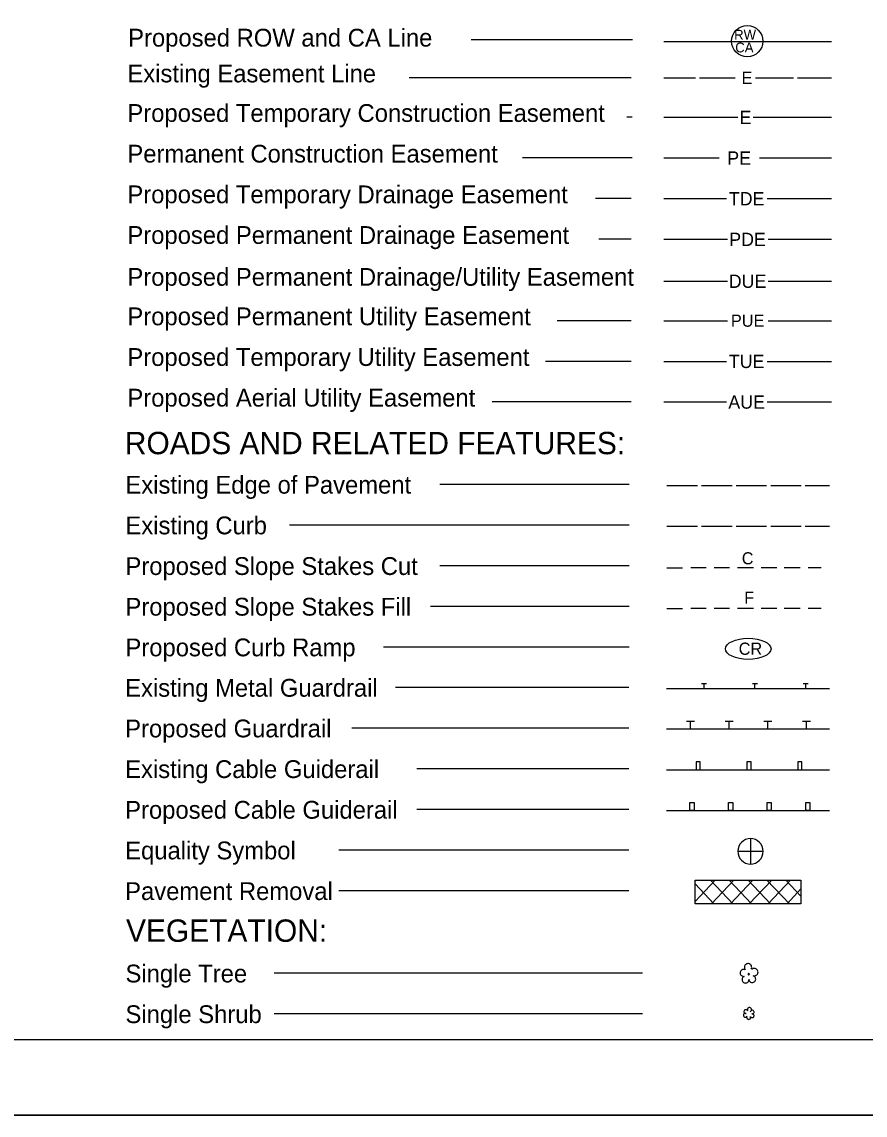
# Model space of a CAD drawing. Extents: x 754056.72 to 754059.56, y 596603.78 to 596605.61.
# Drawn here: x 754057.422 to 754058.119, y 596603.778 to 596604.682 of the extents above; entities that cross this region are included whole.
import ezdxf

# ---------------------------------------------------------------- set-up
doc = ezdxf.new("R2010")
doc.units = 0
for name, color, linetype in [('P_RDY_Easement_Permanent', 7, 'Continuous'), ('P_RDY_Easement_Permanent_Drainage_Utility', 7, 'Continuous'), ('P_RDY_WCC_CELL', 7, 'Continuous'), ('Sheet_Plan', 7, 'Continuous'), ('Sheet_Plot_Border_Outside_CELL', 7, 'Continuous'), ('Sheet_Symbology', 7, 'Continuous'), ('z - Construction', 7, 'Continuous')]:
    doc.layers.add(name, color=color, linetype=linetype)

msp = doc.modelspace()

# ---------------------------------------------------------------- linework, layer by layer
at = {"layer": 'P_RDY_Easement_Permanent'}
for p, q in [((754057.95295, 596604.56986), (754057.99875, 596604.56986)), ((754058.03205, 596604.56986), (754058.07785, 596604.56986)), ((754058.07785, 596604.56986), (754058.09168, 596604.56986))]:
    msp.add_line(p, q, dxfattribs=at)
at = {"layer": 'P_RDY_Easement_Permanent_Drainage_Utility'}
for p, q in [((754057.95295, 596604.46799), (754058.00559, 596604.46799)), ((754058.03922, 596604.46799), (754058.09168, 596604.46799))]:
    msp.add_line(p, q, dxfattribs=at)
at = {"layer": 'P_RDY_WCC_CELL'}
msp.add_ellipse((754058.02274, 596604.16393), major_axis=(0.01886, 0), ratio=0.462467, dxfattribs=at)
at = {"layer": 'Sheet_Plan'}
msp.add_line((754056.78734, 596603.84076), (754059.49562, 596603.84076), dxfattribs=at)
at = {"layer": 'Sheet_Plot_Border_Outside_CELL'}
msp.add_lwpolyline([(754056.72484, 596605.61159), (754059.55817, 596605.61159), (754059.55817, 596603.77826), (754056.72484, 596603.77826)], close=True, dxfattribs=at)
at = {"layer": 'Sheet_Symbology'}
for p, q in [((754057.92706, 596604.66751), (754057.79361, 596604.66751)), ((754057.95297, 596604.66621), (754058.0917, 596604.66621)), ((754057.926, 596604.63621), (754057.74229, 596604.63621)), ((754057.95295, 596604.63621), (754057.97904, 596604.63621)), ((754057.9824, 596604.63621), (754058.01183, 596604.63621)), ((754058.02864, 596604.63621), (754058.06017, 596604.63621)), ((754058.06354, 596604.63621), (754058.09168, 596604.63621)), ((754057.92664, 596604.60349), (754057.92241, 596604.60349)), ((754057.95295, 596604.60349), (754057.95735, 596604.60349)), ((754057.95735, 596604.60349), (754058.0141, 596604.60349)), ((754058.02671, 596604.60349), (754058.08346, 596604.60349)), ((754058.08346, 596604.60349), (754058.09168, 596604.60349)), ((754057.92664, 596604.56986), (754057.83617, 596604.56986)), ((754057.926, 596604.53623), (754057.89657, 596604.53623)), ((754057.95295, 596604.53623), (754057.95859, 596604.53623)), ((754057.95859, 596604.53623), (754058.00483, 596604.53623)), ((754058.03846, 596604.53623), (754058.0847, 596604.53623)), ((754058.0847, 596604.53623), (754058.09168, 596604.53623)), ((754057.926, 596604.5026), (754057.89908, 596604.5026)), ((754057.95295, 596604.5026), (754057.95934, 596604.5026)), ((754057.95934, 596604.5026), (754058.00559, 596604.5026)), ((754058.03922, 596604.5026), (754058.08546, 596604.5026)), ((754058.08546, 596604.5026), (754058.09168, 596604.5026)), ((754057.926, 596604.43532), (754057.86477, 596604.43532)), ((754057.95295, 596604.43532), (754057.95941, 596604.43532)), ((754057.95941, 596604.43532), (754058.00565, 596604.43532)), ((754058.03928, 596604.43532), (754058.08552, 596604.43532)), ((754058.08552, 596604.43532), (754058.09168, 596604.43532)), ((754057.926, 596604.40169), (754057.85514, 596604.40169)), ((754057.95295, 596604.40169), (754057.95859, 596604.40169)), ((754057.95859, 596604.40169), (754058.00483, 596604.40169)), ((754058.03846, 596604.40169), (754058.0847, 596604.40169)), ((754058.0847, 596604.40169), (754058.09168, 596604.40169)), ((754057.926, 596604.36806), (754057.81088, 596604.36806)), ((754057.95295, 596604.36806), (754057.95859, 596604.36806)), ((754057.95859, 596604.36806), (754058.00483, 596604.36806)), ((754058.03846, 596604.36806), (754058.0847, 596604.36806)), ((754058.0847, 596604.36806), (754058.09168, 596604.36806)), ((754057.92438, 596604.29991), (754057.76759, 596604.29991)), ((754057.95554, 596604.29895), (754057.98076, 596604.29895)), ((754057.98413, 596604.29895), (754058.00935, 596604.29895)), ((754058.01271, 596604.29895), (754058.03794, 596604.29895)), ((754058.0413, 596604.29895), (754058.06652, 596604.29895)), ((754058.06989, 596604.29895), (754058.09006, 596604.29895)), ((754057.92438, 596604.26628), (754057.64331, 596604.26628)), ((754057.95554, 596604.26531), (754057.98076, 596604.26531)), ((754057.98413, 596604.26531), (754058.00935, 596604.26531)), ((754058.01271, 596604.26531), (754058.03794, 596604.26531)), ((754058.0413, 596604.26531), (754058.06652, 596604.26531)), ((754058.06989, 596604.26531), (754058.09006, 596604.26531)), ((754057.92438, 596604.23265), (754057.76768, 596604.23265)), ((754057.95554, 596604.23088), (754057.96832, 596604.23088)), ((754057.98799, 596604.23088), (754057.9753, 596604.23088)), ((754058.00733, 596604.23088), (754057.99455, 596604.23088)), ((754058.02709, 596604.23088), (754058.01397, 596604.23088)), ((754058.04634, 596604.23088), (754058.03331, 596604.23088)), ((754058.06577, 596604.23088), (754058.05257, 596604.23088)), ((754058.08309, 596604.23088), (754058.07232, 596604.23088)), ((754057.92438, 596604.19902), (754057.76003, 596604.19902)), ((754057.95554, 596604.19725), (754057.96832, 596604.19725)), ((754057.98799, 596604.19725), (754057.9753, 596604.19725)), ((754058.00733, 596604.19725), (754057.99455, 596604.19725)), ((754058.02709, 596604.19725), (754058.01397, 596604.19725)), ((754058.04634, 596604.19725), (754058.03331, 596604.19725)), ((754058.06577, 596604.19725), (754058.05257, 596604.19725)), ((754058.08309, 596604.19725), (754058.07232, 596604.19725)), ((754057.92438, 596604.16539), (754057.72103, 596604.16539)), ((754057.98409, 596604.13519), (754057.9883, 596604.13519)), ((754057.9862, 596604.13099), (754057.9862, 596604.13519)), ((754058.02613, 596604.13519), (754058.03034, 596604.13519)), ((754058.02823, 596604.13099), (754058.02823, 596604.13519)), ((754058.06817, 596604.13519), (754058.07238, 596604.13519)), ((754058.07027, 596604.13099), (754058.07027, 596604.13519)), ((754057.92412, 596604.13196), (754057.73101, 596604.13196)), ((754057.95528, 596604.13099), (754058.0898, 596604.13099)), ((754057.92412, 596604.09833), (754057.69502, 596604.09833)), ((754057.97163, 596604.104), (754057.97836, 596604.104)), ((754057.97499, 596604.09736), (754057.97499, 596604.104)), ((754058.00358, 596604.104), (754058.01031, 596604.104)), ((754058.00694, 596604.09736), (754058.00694, 596604.104)), ((754058.03553, 596604.104), (754058.04225, 596604.104)), ((754058.03889, 596604.09736), (754058.03889, 596604.104)), ((754058.06748, 596604.104), (754058.0742, 596604.104)), ((754058.07084, 596604.09736), (754058.07084, 596604.104)), ((754058.0898, 596604.09736), (754057.95528, 596604.09736)), ((754057.92412, 596604.0647), (754057.74873, 596604.0647)), ((754057.95528, 596604.06373), (754058.0898, 596604.06373)), ((754057.92412, 596604.03106), (754057.74873, 596604.03106)), ((754057.95528, 596604.0301), (754058.0898, 596604.0301)), ((754058.0246, 596604.00695), (754058.0246, 596603.99644)), ((754057.92412, 596603.99743), (754057.68428, 596603.99743)), ((754058.01409, 596603.99644), (754058.0246, 596603.99644)), ((754058.0246, 596603.99644), (754058.0246, 596603.98593)), ((754058.0246, 596603.99644), (754058.03511, 596603.99644)), ((754057.97873, 596603.97269), (754058.06634, 596603.97269)), ((754057.97873, 596603.95302), (754057.97873, 596603.97269)), ((754057.97873, 596603.97168), (754057.97966, 596603.97269)), ((754057.97873, 596603.95495), (754057.9953, 596603.97269)), ((754058.00993, 596603.95302), (754057.99143, 596603.97269)), ((754057.99244, 596603.95302), (754058.01094, 596603.97269)), ((754058.02548, 596603.95302), (754058.00707, 596603.97269)), ((754058.00799, 596603.95302), (754058.02657, 596603.97269)), ((754058.04112, 596603.95302), (754058.02262, 596603.97269)), ((754058.02363, 596603.95302), (754058.04213, 596603.97269)), ((754058.05676, 596603.95302), (754058.03818, 596603.97269)), ((754058.03927, 596603.95302), (754058.05768, 596603.97269)), ((754058.06634, 596603.95932), (754058.05382, 596603.97269)), ((754058.06634, 596603.97269), (754058.06634, 596603.95302)), ((754057.92412, 596603.9638), (754057.68428, 596603.9638)), ((754057.99429, 596603.95302), (754057.97873, 596603.96967)), ((754058.05482, 596603.95302), (754058.06634, 596603.96529)), ((754058.06634, 596603.95302), (754057.97873, 596603.95302)), ((754057.93518, 596603.89562), (754057.63061, 596603.89562)), ((754057.93518, 596603.86199), (754057.63061, 596603.86199))]:
    msp.add_line(p, q, dxfattribs=at)
for points in [[(754057.97962, 596604.06373), (754057.98298, 596604.06373), (754057.98298, 596604.07045), (754057.97962, 596604.07045)], [(754058.02166, 596604.06373), (754058.02502, 596604.06373), (754058.02502, 596604.07045), (754058.02166, 596604.07045)], [(754058.06369, 596604.06373), (754058.06706, 596604.06373), (754058.06706, 596604.07045), (754058.06369, 596604.07045)], [(754057.97455, 596604.03682), (754057.97791, 596604.03682), (754057.97791, 596604.0301), (754057.97455, 596604.0301)], [(754058.0065, 596604.03682), (754058.00986, 596604.03682), (754058.00986, 596604.0301), (754058.0065, 596604.0301)], [(754058.03845, 596604.03682), (754058.04181, 596604.03682), (754058.04181, 596604.0301), (754058.03845, 596604.0301)], [(754058.0704, 596604.03682), (754058.07376, 596604.03682), (754058.07376, 596604.0301), (754058.0704, 596604.0301)]]:
    msp.add_lwpolyline(points, close=True, dxfattribs=at)
for points in [[(754058.0252, 596603.89913), (754058.02547, 596603.89973), (754058.0256, 596603.90032), (754058.02553, 596603.90099), (754058.0254, 596603.90158), (754058.02507, 596603.90218), (754058.02474, 596603.90264), (754058.02421, 596603.90311), (754058.02368, 596603.90337), (754058.02302, 596603.90357), (754058.02242, 596603.90357), (754058.02176, 596603.9035), (754058.02116, 596603.9033), (754058.02064, 596603.90297), (754058.02017, 596603.90251), (754058.01984, 596603.90198), (754058.01958, 596603.90138), (754058.01951, 596603.90079), (754058.01951, 596603.90013), (754058.01964, 596603.89953), (754058.01991, 596603.89894), (754058.0203, 596603.89841), (754058.01977, 596603.89867), (754058.01918, 596603.8988), (754058.01858, 596603.89874), (754058.01799, 596603.8986), (754058.01746, 596603.89834), (754058.01693, 596603.89794), (754058.0166, 596603.89748), (754058.01626, 596603.89695), (754058.01613, 596603.89642), (754058.01607, 596603.89576), (754058.01613, 596603.89516), (754058.0164, 596603.89463), (754058.01673, 596603.8941), (754058.01713, 596603.8937), (754058.01766, 596603.89337), (754058.01819, 596603.89311), (754058.01878, 596603.89304), (754058.01938, 596603.89304), (754058.01885, 596603.89278), (754058.01839, 596603.89238), (754058.01805, 596603.89192), (754058.01779, 596603.89132), (754058.01766, 596603.89073), (754058.01759, 596603.89013), (754058.01772, 596603.88953), (754058.01799, 596603.889), (754058.01832, 596603.88847), (754058.01871, 596603.88808), (754058.01924, 596603.88775), (754058.01984, 596603.88755), (754058.02044, 596603.88748), (754058.02103, 596603.88755), (754058.02163, 596603.88768), (754058.02216, 596603.88801), (754058.02262, 596603.88841), (754058.02295, 596603.88887), (754058.02322, 596603.8894), (754058.02335, 596603.89)], [(754058.02315, 596603.89073), (754058.02322, 596603.89006), (754058.02342, 596603.88947), (754058.02375, 596603.88894), (754058.02421, 596603.88847), (754058.02474, 596603.88814), (754058.02533, 596603.88795), (754058.026, 596603.88788), (754058.02659, 596603.88795), (754058.02719, 596603.88814), (754058.02772, 596603.88847), (754058.02818, 596603.88887), (754058.02858, 596603.8894), (754058.02878, 596603.89), (754058.02891, 596603.89059), (754058.02884, 596603.89126), (754058.02871, 596603.89185), (754058.02838, 596603.89245), (754058.02798, 596603.89291), (754058.02745, 596603.89324), (754058.02686, 596603.89351), (754058.02752, 596603.89344), (754058.02818, 596603.89344), (754058.02878, 596603.89364), (754058.02937, 596603.8939), (754058.0299, 596603.8943), (754058.0303, 596603.89483), (754058.03063, 596603.89543), (754058.03077, 596603.89602), (754058.03083, 596603.89668), (754058.0307, 596603.89735), (754058.0305, 596603.89794), (754058.0301, 596603.89847), (754058.02964, 596603.89894), (754058.02911, 596603.89927), (754058.02845, 596603.89953), (754058.02785, 596603.8996), (754058.02719, 596603.8996), (754058.02653, 596603.8994), (754058.026, 596603.89907), (754058.02547, 596603.89867)], [(754058.02335, 596603.89543), (754058.02308, 596603.89543), (754058.02282, 596603.89536), (754058.02269, 596603.89516), (754058.02262, 596603.8949), (754058.02269, 596603.89463), (754058.02289, 596603.89443), (754058.02315, 596603.89443), (754058.02342, 596603.8945), (754058.02361, 596603.8947), (754058.02368, 596603.89496), (754058.02355, 596603.89523), (754058.02335, 596603.89543)], [(754058.02236, 596603.86444), (754058.02216, 596603.86484), (754058.02176, 596603.86517), (754058.02136, 596603.86544), (754058.0209, 596603.8655), (754058.02044, 596603.86544), (754058.01997, 596603.8653), (754058.01958, 596603.86497), (754058.01931, 596603.86457), (754058.01918, 596603.86411), (754058.01918, 596603.86365), (754058.01931, 596603.86319), (754058.01958, 596603.86279), (754058.01997, 596603.86246), (754058.02044, 596603.86226), (754058.0209, 596603.86226), (754058.02044, 596603.86232), (754058.01997, 596603.86232), (754058.01958, 596603.86219), (754058.01918, 596603.86193), (754058.01892, 596603.8616), (754058.01878, 596603.8612), (754058.01871, 596603.86073), (754058.01878, 596603.86027), (754058.01898, 596603.85987), (754058.01931, 596603.85954), (754058.01971, 596603.85935), (754058.02011, 596603.85921), (754058.02057, 596603.85928), (754058.02097, 596603.85941), (754058.02136, 596603.85968), (754058.02163, 596603.86001), (754058.02143, 596603.85954), (754058.02136, 596603.85908), (754058.0215, 596603.85862), (754058.02169, 596603.85822), (754058.02202, 596603.85782), (754058.02242, 596603.85762), (754058.02289, 596603.85749), (754058.02335, 596603.85756), (754058.02381, 596603.85769), (754058.02421, 596603.85795), (754058.02448, 596603.85835), (754058.02467, 596603.85882), (754058.02467, 596603.85928), (754058.02461, 596603.85974), (754058.02481, 596603.85941), (754058.0252, 596603.85908), (754058.0256, 596603.85895), (754058.02606, 596603.85888), (754058.02653, 596603.85895), (754058.02692, 596603.85915), (754058.02726, 596603.85948), (754058.02745, 596603.85987), (754058.02752, 596603.86034), (754058.02752, 596603.8608), (754058.02732, 596603.8612), (754058.02706, 596603.86153), (754058.02673, 596603.86179), (754058.02626, 596603.86199), (754058.0258, 596603.86199), (754058.02626, 596603.86199), (754058.02673, 596603.86213), (754058.02706, 596603.86239), (754058.02739, 596603.86279), (754058.02752, 596603.86319), (754058.02752, 596603.86365), (754058.02745, 596603.86411), (754058.02719, 596603.86451), (754058.02686, 596603.86477), (754058.02639, 596603.86497), (754058.02593, 596603.86504), (754058.02553, 596603.86491), (754058.02507, 596603.86471), (754058.02481, 596603.86438), (754058.02461, 596603.86398)], [(754058.02441, 596603.86398), (754058.02481, 596603.86418), (754058.02514, 596603.86457), (754058.02533, 596603.86497), (754058.0254, 596603.86544), (754058.0254, 596603.8659), (754058.0252, 596603.86636), (754058.02494, 596603.86669), (754058.02461, 596603.86702), (754058.02414, 596603.86716), (754058.02368, 596603.86722), (754058.02322, 596603.86716), (754058.02282, 596603.86696), (754058.02242, 596603.86663), (754058.02222, 596603.86623), (754058.02209, 596603.86577), (754058.02209, 596603.8653), (754058.02216, 596603.86484), (754058.02242, 596603.86444)]]:
    msp.add_lwpolyline(points, dxfattribs=at)
msp.add_circle((754058.0219, 596604.66647), 0.01298, dxfattribs=at)
for start, end in [(89.99439, 179.99893), (359.99439, 89.99893), (179.99439, 269.99892), (269.99439, 359.99893)]:
    msp.add_arc((754058.0246, 596603.99644), 0.01051, start, end, dxfattribs=at)
at = {"layer": 'z - Construction'}
msp.add_line((754056.72484, 596603.77826), (754059.55817, 596603.77826), dxfattribs=at)

# ---------------------------------------------------------------- texts
at = {"layer": 'P_RDY_Easement_Permanent_Drainage_Utility'}
msp.add_text('DUE', height=0.011014, dxfattribs=at).set_placement((754058.00659, 596604.46244))
at = {"layer": 'P_RDY_WCC_CELL'}
msp.add_text('CR', height=0.010089, dxfattribs=at).set_placement((754058.01482, 596604.15896))
at = {"layer": 'Sheet_Symbology'}
for s, height, p in [('Proposed ROW and CA Line', 0.0147137, (754057.51, 596604.662)), ('RW', 0.008136, (754058.01105, 596604.66776)), ('CA', 0.008136, (754058.01199, 596604.65718)), ('Existing Easement Line', 0.0147137, (754057.50939, 596604.6324)), ('E', 0.01009, (754058.01721, 596604.63116)), ('Proposed Temporary Construction Easement', 0.0147137, (754057.50939, 596604.59969)), ('E', 0.01101, (754058.01554, 596604.59794)), ('Permanent Construction Easement', 0.0147137, (754057.50939, 596604.56606)), ('PE', 0.011014, (754058.00538, 596604.56431)), ('Proposed Temporary Drainage Easement', 0.0147137, (754057.50939, 596604.53243)), ('TDE', 0.011014, (754058.00669, 596604.53068)), ('Proposed Permanent Drainage Easement', 0.0147137, (754057.50939, 596604.4988)), ('PDE', 0.011014, (754058.00702, 596604.49705)), ('Proposed Permanent Drainage/Utility Easement', 0.0147137, (754057.50939, 596604.46419)), ('Proposed Permanent Utility Easement', 0.0147137, (754057.50939, 596604.43152)), ('PUE', 0.010089, (754058.00835, 596604.43028)), ('Proposed Temporary Utility Easement', 0.0147137, (754057.50939, 596604.39789)), ('TUE', 0.011014, (754058.00669, 596604.39614)), ('Proposed Aerial Utility Easement', 0.0147137, (754057.50939, 596604.36426)), ('AUE', 0.011014, (754058.00626, 596604.36251)), ('ROADS AND RELATED FEATURES:', 0.0184972, (754057.50727, 596604.32487)), ('Existing Edge of Pavement', 0.0147137, (754057.50777, 596604.29226)), ('Existing Curb', 0.0147137, (754057.50777, 596604.25863)), ('C', 0.00997, (754058.01742, 596604.23381)), ('Proposed Slope Stakes Cut', 0.0147137, (754057.50777, 596604.225)), ('Proposed Slope Stakes Fill', 0.0147137, (754057.50777, 596604.19137)), ('F', 0.00997, (754058.01944, 596604.20123)), ('Proposed Curb Ramp', 0.0147137, (754057.50777, 596604.15774)), ('Existing Metal Guardrail', 0.0147137, (754057.50751, 596604.12431)), ('Proposed Guardrail', 0.0147137, (754057.50753, 596604.0907)), ('Existing Cable Guiderail', 0.0147137, (754057.50753, 596604.05706)), ('Proposed Cable Guiderail', 0.0147137, (754057.50753, 596604.02343)), ('Equality Symbol', 0.0147137, (754057.50753, 596603.9898)), ('Pavement Removal', 0.0147137, (754057.50753, 596603.95617)), ('VEGETATION:', 0.0184972, (754057.50825, 596603.9216)), ('Single Tree', 0.0147137, (754057.50779, 596603.88802)), ('Single Shrub', 0.0147137, (754057.50779, 596603.85438))]:
    msp.add_text(s, height=height, dxfattribs=at).set_placement(p)

doc.saveas('drawing.dxf')
